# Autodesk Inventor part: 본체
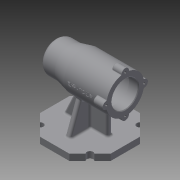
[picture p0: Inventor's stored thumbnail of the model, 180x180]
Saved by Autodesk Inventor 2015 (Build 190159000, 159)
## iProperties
Created: 2019-12
Part Number: 본체
Material: 일반
Document SubType Name: Modeling
Designer: 101548
Density: 1 g/cm^3
Appearance: 기본값
Author: 101548
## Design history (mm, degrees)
sketch "스케치1" dims "d0" = 112
  geometry: L1 (23.196, 56)-(56, 23.196); L2 (56, 23.196)-(56, -23.196); L3 (56, -23.196)-(23.196, -56); L4 (23.196, -56)-(-23.196, -56); L5 (-23.196, -56)-(-56, -23.196); L6 (-56, -23.196)-(-56, 23.196); L7 (-56, 23.196)-(-23.196, 56); L8 (-23.196, 56)-(23.196, 56); 4 further points
  constraints: 16 end point, 2 coincident, 1 midpoint, 1 vertical alignment, 19 other
extrude "돌출1" new body sketch "스케치1" distance "d1" = 10; taper "d2" = 0 deg
sketch "스케치2"
  geometry: L1 (-56, -23.196)-(-23.196, -56) reference; C1 r 5 at (-39.598, -39.598); 1 further point
  constraints: 1 centre point, 1 midpoint
  dimensions: "d3" = 10 diameter of C1
extrude "돌출2" cut sketch "스케치2" stored distance "d4" = 10; taper "d5" = 0 deg
sketch "스케치3"
  geometry: L1 (-56, 23.196)-(-23.196, 56) reference; L2 (23.196, 56)-(56, 23.196) reference; L3 (56, -23.196)-(23.196, -56) reference; C1 r 5 at (-39.598, 39.598); C2 r 5 at (39.598, 39.598); C3 r 5 at (39.598, -39.598); 1 further point
  constraints: 3 centre point, 3 midpoint
  dimensions: "d6" = 10 diameter of C1; "d7" = 10 diameter of C2; "d8" = 10 diameter of C3
extrude "돌출3" cut sketch "스케치3" stored distance "d9" = 10; taper "d10" = 0 deg
sketch "스케치4"
  geometry: L1 (56, -23.196)-(56, 23.196) reference; L2 (23.196, 56)-(-23.196, 56) reference; L3 (-56, 23.196)-(-56, -23.196) reference; L4 (-23.196, -56)-(23.196, -56) reference; L5 (-38, -4)-(31, -4); L6 (31, -4)-(31, 4); L7 (31, 4)-(-38, 4); L8 (-38, 4)-(-38, -4); L9 (-4, -36)-(4, -36); L10 (4, -36)-(4, 36); L11 (4, 36)-(-4, 36); L12 (-4, 36)-(-4, -36); 1 further point
  constraints: 16 end point, 4 parallel, 2 horizontal, 2 perpendicular
  dimensions: "d11" = 4 distance from line of L7 point (0, 0); "d12" = 8 distance of L5.end L6.end; "d13" = 4 distance from line of L10 point (0, 0); "d14" = 8 distance of L9.start L9.end; "d15" = 25 distance between parallel lines of L1 L6; "d16" = 18 distance between parallel lines of L3 L8; "d17" = 20 distance between parallel lines of L4 L9; "d18" = 20 distance between parallel lines of L2 L11
extrude "돌출4" join sketch "스케치4" distance "d19" = 70; taper "d20" = 0 deg
feature "면 기울기1" dims angle "d21" = 20 deg
feature "면 기울기2" dims angle "d22" = 25 deg
sketch "스케치5"
  geometry: L1 (56, 0)-(-56, 0) reference; L2 (-56, 0)-(-56, 10) reference; L3 (-56, 10)-(-31, 10) reference; L4 (-31, 10)-(-31, 80) reference; L5 (-31, 80)-(5.358, 80) reference; L6 (5.358, 80)-(38, 10) reference; L7 (38, 10)-(56, 10) reference; L8 (56, 10)-(56, 0) reference; L9 (56, 80)-(-56, 80); L10 (-56, 80)-(-56, 110); L11 (-56, 110)-(11, 110); L12 (11, 110)-(31, 105); L13 (31, 105)-(56, 105); L14 (56, 105)-(56, 80); 3 further points
  constraints: 12 end point, 3 perpendicular, 2 midpoint, 1 collinear, 1 horizontal, 1 parallel, 1 vertical alignment
  dimensions: "d23" = 30 distance of L9.end L10.end; "d24" = 25 distance of L13.end L9.start; "d25" = 112 distance of L9.start L9.end; "d26" = 25 distance of L12.end L13.end; "d27" = 45 horizontal distance of L11.end L13.end
revolve "회전1" sketch "스케치5" stored, may be unused: angle "d28" = 90 deg
sketch "스케치6"
  geometry: C1 r 6 at (-30, 0); 2 further points
  constraints: 1 centre point, 1 horizontal alignment, 1 other
  dimensions: "d29" = 12 diameter of C1
extrude "돌출5" join sketch "스케치6" distance "d30" = 16; taper "d31" = 0 deg
fillet "모깎기1" dims "d32" = 3
fillet "모깎기2" dims "d33" = 1
sketch "스케치7"
  geometry: C1 r 21 at (30, 0); A1 r 30 centre (30, 0) between (36.771, -29.226) and (59.226, -6.771) reference; 1 further point
  constraints: 1 centre point, 1 coincident
  dimensions: "d37" = 42 diameter of C1
extrude "돌출6" cut sketch "스케치7" distance "d38" = 15; taper "d39" = 0 deg
sketch "스케치8"
  geometry: C1 r 21 at (0, 0) reference; C2 r 24 at (0, 0); 1 further point
  constraints: 1 centre point, 1 coincident
  dimensions: "d40" = 48 diameter of C2
extrude "돌출7" cut sketch "스케치8" distance "d41" = 54; taper "d42" = 0 deg
sketch "스케치9"
  geometry: C1 r 24 at (0, 0) reference; C2 r 21 at (0, 0); 1 further point
  constraints: 1 centre point, 1 coincident
  dimensions: "d43" = 42 diameter of C2
extrude "돌출8" cut sketch "스케치9" distance "d44" = 12; taper "d45" = 0 deg
sketch "스케치10"
  geometry: C1 r 21 at (0, 0) reference; C2 r 17.5 at (0, 0); 1 further point
  constraints: 1 centre point, 1 coincident
  dimensions: "d46" = 35 diameter of C2
extrude "돌출9" cut sketch "스케치10" distance "d47" = 18; taper "d48" = 0 deg
sketch "스케치11"
  geometry: C1 r 17.5 at (0, 0) reference; C2 r 16 at (0, 0); 1 further point
  constraints: 1 centre point, 1 coincident
  dimensions: "d49" = 32 diameter of C2
extrude "돌출10" cut sketch "스케치11" distance "d50" = 4; taper "d51" = 0 deg
sketch "스케치12"
  geometry: C1 r 16 at (0, 0) reference; C2 r 10.5 at (0, 0); 1 further point
  constraints: 1 centre point, 1 coincident
  dimensions: "d52" = 21 diameter of C2
extrude "돌출11" cut sketch "스케치12" distance "d53" = 3; taper "d54" = 0 deg
fillet "모깎기3" dims "d55" = 3
fillet "모깎기4" dims "d56" = 0.3
fillet "모깎기5" dims "d57" = 3
chamfer "모따기1" distance "d58" = 1; stored, may be unused: second distance "d59" = 2, angle "d60" = 45 deg
sketch "스케치13"
  geometry: A1 r 6 centre (0, 0) between (-0.171, 5.998) and (-0.171, -5.998) reference; 1 further point
hole "구멍1" sketch "스케치13" at (0, 0) diameter "d61" = 3.242; stored, may be unused: countersink angle "d65" = 90 deg, drill point angle "d67" = 118 deg; dims "d62" = 8, "d63" = 4, "d64" = 2, "d66" = 11
fillet "모깎기6" dims "d71" = 10
fillet "모깎기7" dims "d72" = 3
fillet "모깎기8" dims "d73" = 3
fillet "모깎기9" dims "d74" = 3
fillet "모깎기10" dims "d75" = 3
node "작업 평면1"
sketch "스케치14"
  geometry: L1 (33.5, 36)-(33.5, 30.171) reference; L2 (33.5, 5.998)-(33.5, -5.998) reference; 3 further points
  constraints: 1 horizontal alignment, 1 midpoint, 1 other
  dimensions: "d76" = 41 distance from line of L1 point (-7.5, 0)
feature "엠보싱1" sketch "스케치14" dims "d77" = 0.5, "d78" = 0
node "솔리드1"
pattern_circular "원형 패턴1" dims "d35" = 360 deg
pattern_circular "원형 패턴2" dims angle "d69" = 360 deg
node "절단 모서리 투영1"
